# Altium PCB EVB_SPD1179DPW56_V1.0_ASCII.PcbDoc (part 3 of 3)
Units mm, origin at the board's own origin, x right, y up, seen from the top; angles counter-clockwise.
Board outline 135 x 90 mm, 4 copper layers (Top Layer, GND, L3, Bottom Layer), stack 0.603 mm thick; 336 components, 177 nets, 814 pads, 1056 vias.
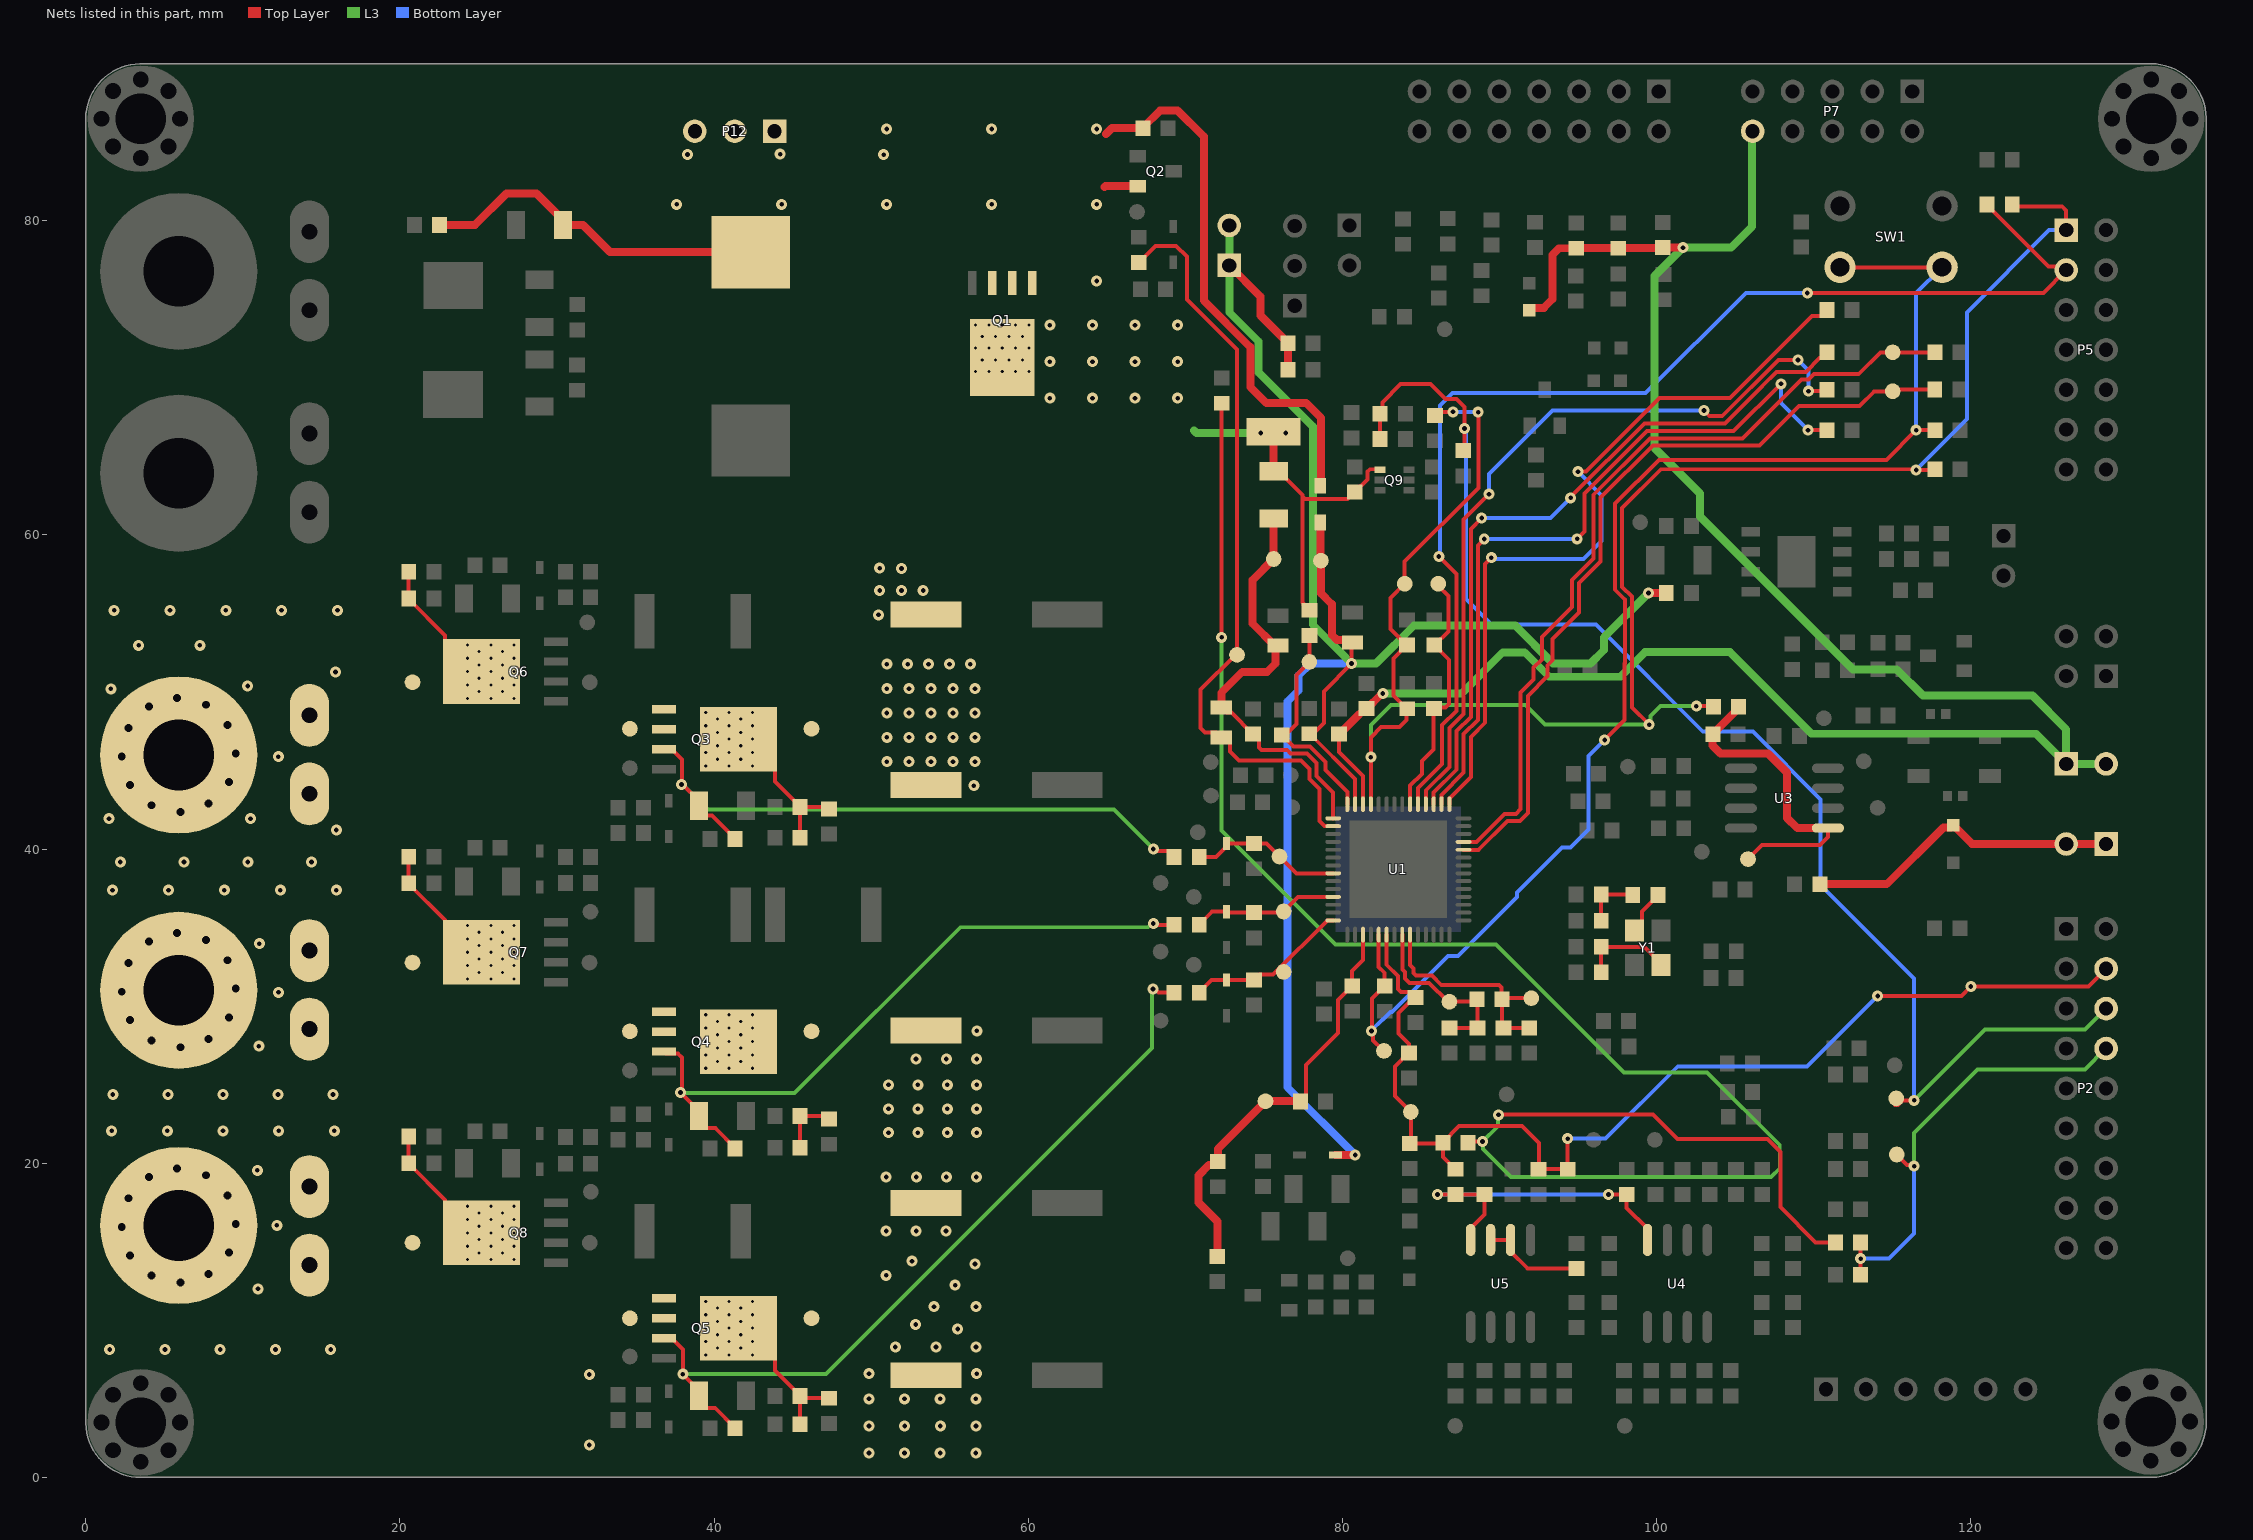
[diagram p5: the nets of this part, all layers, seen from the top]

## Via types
v1: diameter 0.7, hole 0.3, Top Layer to Bottom Layer, tented both sides, 810 vias
v2: diameter 0.5, hole 0.2, Top Layer to Bottom Layer, tented both sides, 161 vias
v3: diameter 0.9, hole 0.5, Top Layer to Bottom Layer, 60 vias
v4: diameter 0.6, hole 0.3, Top Layer to Bottom Layer, tented top, 25 vias

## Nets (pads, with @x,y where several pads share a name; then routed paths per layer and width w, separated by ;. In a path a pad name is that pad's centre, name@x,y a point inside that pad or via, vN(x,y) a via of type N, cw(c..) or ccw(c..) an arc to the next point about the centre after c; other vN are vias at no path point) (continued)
NetR107_1: R107.1 R108.1 R109.1 | length 123.1
  Top Layer w0.254: v1(72.314,53.487) R109.1@72.314,68.39 R109.1@72.466,68.237 ; R107.1@87.998,21.311 88.072,21.384 v1(88.925,21.384) ; v1(89.941,23.089) 89.967,23.114 99.771,23.114 101.346,21.539 107.075,21.539 107.885,20.729 107.885,17.207 110.132,14.961 R108.1@111.392,14.961 R108.1@111.392,14.986
  L3 w0.254: v1(72.314,53.487) 72.314,41.173 79.553,33.934 89.789,33.934 97.942,25.781 103.226,25.781 107.848,21.158 107.848,19.681 107.293,19.126 90.729,19.126 88.961,20.894 88.961,21.349 v1(88.925,21.384) 89.899,22.358 89.899,23.046 v1(89.941,23.089)
NetR110_2: R110.2 U5.6 U5.7 | length 6.6
  Top Layer w0.254: U5.7@89.443,15.117 U5.6@90.713,15.117 90.713,14.388 91.804,13.297 R110.2@94.904,13.297
NetR123_1: R123.1 Y1.3 | length 2.9
  Top Layer w0.254: Y1.3@98.591,34.831 99.064,35.304 99.064,36.034 100.089,37.059 R123.1@100.089,37.084
NTCAD: C73.2 P2.8 R108.2 TP51.1 | length 28.5
  Top Layer w0.254: C73.2@112.992,12.903 R108.2@112.992,14.961 R108.2@112.992,14.986 ; TP51.1@115.3,20.559 115.962,19.897 116.323,19.897 v1(116.408,19.812) v1@116.288,19.812
  L3 w0.254: v1(116.408,19.812) 116.408,21.94 120.452,25.983 127.269,25.983 128.591,27.305 P2.8@128.626,27.305
  Bottom Layer w0.254: v1(113.005,13.924) 114.812,13.924 116.408,15.519 v1(116.408,19.812)
PGAIN: C51.1 C53.2 R58.2 TP49.1 U1.50 | length 11.7
  Top Layer w0.254: U1.50@83.816,34.56 83.816,32.347 83.997,32.166 83.997,31.761 84.273,31.484 85.521,31.484 86.721,30.284 TP49.1@86.818,30.284 88.415,30.284 C51.1@88.567,30.437 88.605,30.399 R58.2@88.605,28.621 C53.2@86.827,28.621
PGAIP: C51.2 C52.2 R54.2 TP46.1 U1.51 | length 14.7
  Top Layer w0.254: U1.51@84.316,34.56 84.316,32.62 84.538,32.397 84.538,32.1 84.687,31.951 85.701,31.951 86.298,31.354 89.989,31.354 90.138,31.205 90.138,30.619 C51.2@90.243,30.513 ; C52.2@91.907,28.621 R54.2@90.256,28.621 90.167,28.71 C51.2@90.167,30.437 C51.2@90.243,30.513 ; TP46.1@92.034,30.513 C51.2@90.243,30.513
PWM/LIN: D18.2 P25.1 P25.2 R21.1 | length 20.3
  Top Layer w0.508: R21.1@110.401,37.77 114.656,37.77 118.271,41.385 118.751,41.385 D18.2@118.897,41.531 120.101,40.327 P25.2@126.086,40.327 P25.1@128.626,40.327
PWM/LIN_MCU: C78.2 R66.2 R84.1 R111.1 TP50.1 U1.45 | length 26.8
  Top Layer w0.254: R66.2@77.305,23.952 77.331,23.952 77.678,24.3 77.678,26.269 79.718,28.308 79.718,30.394 80.604,31.28 80.604,32.234 81.316,32.946 U1.45@81.316,34.56
  Top Layer w0.508: R84.1@72.044,14.075 72.044,16.293 70.842,17.495 70.842,19.229 71.496,19.883 71.848,19.883 R111.1@72.069,20.104 72.069,20.914 TP50.1@75.108,23.952 R66.2@77.305,23.952
TCK/SWC: R16.2 U1.18 | length 49.1
  Top Layer w0.254: U1.18@85.316,42.86 85.316,43.749 86.81,45.243 86.81,47.705 87.72,48.615 87.72,60.977 v1(89.339,62.597) ; v1(103.022,67.921) 103.383,67.561 104.176,67.561 107.76,71.145 v1(109.017,71.145) ; v1(109.677,69.159) 110.777,69.159 R16.2@110.858,69.24
  Bottom Layer w0.254: v1(89.339,62.597) 89.339,63.882 93.379,67.921 v1(103.022,67.921) ; v1(109.017,71.145) 109.677,70.485 v1(109.677,69.159)
TDI: R13.2 U1.15 | length 49.5
  Top Layer w0.254: U1.15@86.816,42.86 86.816,43.231 88.182,44.597 88.182,47.137 89.091,48.046 89.091,58.162 v1(89.483,58.554) ; v1(95.001,64.033) 95.518,64.033 100.201,68.716 104.685,68.716 109.916,73.947 110.51,73.947 110.858,74.295 R13.2@110.858,74.32
  Bottom Layer w0.254: v1(89.483,58.554) 89.558,58.479 95.369,58.479 96.514,59.624 96.514,62.521 v1(95.001,64.033)
TDO: R18.2 U1.16 | length 47.3
  Top Layer w0.254: U1.16@86.316,42.86 86.318,42.862 86.318,43.457 87.725,44.864 87.725,47.327 88.634,48.236 88.634,59.343 v1(89.035,59.744) ; v1(94.951,59.758) 95.409,60.216 95.409,62.631 99.391,66.614 104.909,66.614 v1(107.923,69.628) ; v1(109.652,66.675) 110.85,66.675 R18.2@110.858,66.667
  Bottom Layer w0.254: v1(89.035,59.744) 89.042,59.751 94.944,59.751 v1(94.951,59.758) ; v1(107.923,69.628) 107.923,68.404 v1(109.652,66.675)
TMS/SWD: R14.2 U1.17 | length 45.9
  Top Layer w0.254: U1.17@85.816,42.86 85.816,43.602 87.268,45.054 87.268,47.516 88.177,48.425 88.177,60.383 v1(88.876,61.082) ; v1(94.54,62.365) 94.54,62.409 99.235,67.103 104.372,67.103 106.731,69.463 106.731,69.47 107.645,70.383 109.513,70.383 110.385,71.255 110.51,71.255 110.858,71.603 R14.2@110.858,71.628
  Bottom Layer w0.254: v1(88.876,61.082) 93.257,61.082 v1(94.54,62.365)
TRSTn: P5.3 R12.1 U1.19 | length 77.1
  Top Layer w0.254: U1.19@84.816,42.86 84.816,43.895 86.353,45.432 86.353,47.895 87.262,48.804 87.262,57.518 v1(86.146,58.635) ; v1(109.607,75.413) 124.628,75.413 P5.3@126.086,76.87 125.847,77.108 124.964,77.108 121.052,81.02 R12.1@121.052,81.045
  Bottom Layer w0.254: v1(86.146,58.635) 86.227,58.716 86.227,68.246 87.015,69.033 99.309,69.033 105.689,75.413 v1(109.607,75.413)
UART_RX: R15.1 TP60.1 U1.11 | length 51.9
  Top Layer w0.254: U1.11@87.716,40.46 88.531,40.46 90.318,42.247 91.055,42.247 91.349,42.54 91.349,49.958 92.178,50.788 92.178,51.559 92.705,52.086 92.705,53.511 94.611,55.417 94.611,57.139 95.987,58.515 95.987,62.562 99.581,66.156 105.485,66.156 109.219,69.89 109.666,69.89 110.033,70.256 112.878,70.256 114.249,71.628 TP60.1@115.037,71.628 R15.1@117.729,71.628
UART_TX: R17.1 TP59.1 U1.10 | length 51.2
  Top Layer w0.254: U1.10@87.716,39.96 88.673,39.96 90.503,41.79 91.309,41.79 91.806,42.286 91.806,49.764 93.06,51.018 93.06,51.706 93.38,52.026 93.38,53.367 95.069,55.056 95.069,56.95 96.444,58.325 96.444,62.373 99.77,65.699 106.568,65.699 109.068,68.199 112.916,68.199 113.864,69.147 TP59.1@115.037,69.147 115.155,69.266 R17.1@117.716,69.266
VBAT: C35.2 C36.2 D12.1 D16.2 P11.1 P11.2 R49.1 R113.2 R114.1 TP55.1 U1.27 | length 122.2
  Top Layer w0.254: C36.2@77.9,47.347 77.925,47.347 80.816,44.456 U1.27@80.816,42.86 ; C36.2@78.127,47.322 78.829,48.024 78.829,50.05 80.582,51.804 v1(80.582,51.816) C35.2@80.582,53.101
  Top Layer w0.508: P11.1@72.803,77.168 74.797,75.174 74.797,73.971 76.544,72.224 R113.2@76.544,72.199 76.541,72.196 76.541,70.528 R114.1@76.537,70.524 ; D12.1@78.595,60.798 78.595,58.412 TP55.1@78.638,58.369 78.638,56.286 79.329,55.596 79.329,53.646 79.659,53.316 80.367,53.316 C35.2@80.582,53.101 ; D16.2@79.559,20.523 D16.2@79.559,20.523 80.82,20.522 v1(80.821,20.521) ; v1(99.492,56.312) R49.1@100.622,56.312
  L3 w0.508: P11.2@72.803,79.221 P11.1@72.803,77.168 72.803,74.181 74.675,72.309 74.675,70.345 78.121,66.9 78.121,54.29 80.582,51.828 v1(80.582,51.816) ; v1@80.594,51.816 82.138,51.816 84.572,54.25 90.984,54.25 93.419,51.816 95.8,51.816 96.649,52.665 96.649,53.469 v1(99.492,56.312)
  Bottom Layer w0.508: v1(80.582,51.816) 77.968,51.816 77.195,51.043 77.195,50.085 76.497,49.387 76.497,24.845 v1(80.821,20.521)
VBAT1: C9.2 C10.1 C11.2 D12.2 L1.2 P12.1 P12.2 P12.3 Q1.1 Q1.2 Q1.3 Q2.2 | length 58.9
  Top Layer w0.508: C11.2@22.517,79.731 24.77,79.731 26.781,81.742 28.694,81.742 30.059,80.377 30.38,80.056 C10.1@30.38,79.731 31.648,79.731 33.37,78.009 L1.2@42.342,78.009 ; 64.872,82.169 64.912,82.21 Q2.2@66.973,82.21 ; 64.948,85.522 65.329,85.903 C9.2@67.297,85.903 67.297,85.928 68.403,87.033 69.507,87.033 71.178,85.362 71.178,74.923 74.143,71.958 74.143,69.418 75.159,68.402 77.699,68.402 78.638,67.462 D12.2@78.638,63.143
  other v1: 64.364,76.175 37.617,81.051 44.304,81.051 50.99,81.051 57.677,81.051 64.364,81.051 50.799,84.212 38.309,84.222 44.209,84.243 50.99,85.852 57.677,85.852 64.364,85.852
VBAT_D: C1.1 C5.1 C6.1 C14.1 C15.1 C16.2 C17.2 C18.2 C20.2 C21.2 C22.2 C56.1 C68.1 C69.1 Q1.5 Q3.5 Q4.5 Q5.5 Q9.4 R39.2 R43.1 R93.1 TP4.1 TP5.1 TP6.1 TP40.1 | length 45.2
  Top Layer w0.254: v2(42.443,7.804) 43.631,7.804 43.866,7.569 43.866,6.819 45.479,5.207 C22.2@45.479,5.182 ; v2(42.443,45.301) 43.631,45.301 43.866,45.066 43.866,44.316 45.479,42.704 C20.2@45.479,42.679 ; C69.1@45.479,3.378 C22.2@45.479,5.182 ; C68.1@45.479,20.996 C21.2@45.479,23.003 47.13,23.003 C16.2@47.32,22.812 ; C56.1@45.479,40.723 C20.2@45.479,42.679 ; C18.2@47.32,5.042 45.618,5.042 C22.2@45.479,5.182 ; C17.2@47.32,42.564 47.206,42.679 C20.2@45.479,42.679 ; R43.1@75.625,64.06 75.95,64.06 77.47,62.54 77.47,62.461 ; R39.2@77.911,55.207 77.886,55.207 77.538,55.555 77.538,55.635 77.47,55.704 77.47,62.461 ; Q9.4@82.392,64.15 82.337,64.094 82.245,64.186 81.759,64.186 81.61,64.037 81.61,63.532 81.154,63.076 81.104,63.076 80.335,62.306 77.625,62.306 77.47,62.461
  Top Layer w0.508: R43.1@75.625,64.06 TP40.1@75.625,66.573
  L3 w0.508: 70.561,66.65 70.714,66.497 v1(74.799,66.497) v1(76.399,66.497)
  other v1: 49.86,1.549 52.129,1.549 54.398,1.549 56.667,1.549 32.055,2.057 49.86,3.277 52.132,3.277 54.404,3.277 56.676,3.277 49.86,5.004 52.129,5.004 54.398,5.004 56.667,5.004 32.055,6.553 49.86,6.604 56.718,6.604 51.537,8.306 54.131,8.306 56.676,8.306 55.506,9.451 52.832,9.728 54,10.871 56.676,10.871 55.347,12.243 50.961,12.866 56.617,13.589 52.603,13.767 50.961,15.686 52.866,15.686 54.771,15.686 50.961,19.126 52.874,19.126 54.787,19.126 56.701,19.126 51.105,21.946 52.976,21.946 54.847,21.946 56.718,21.946 51.105,23.47 52.976,23.47 54.847,23.47 56.718,23.47 51.105,24.994 52.976,24.994 54.847,24.994 56.718,24.994 52.857,26.645 54.788,26.645 56.718,26.645 56.726,28.436 56.54,44.044 51.003,45.568 52.407,45.568 53.81,45.568 55.213,45.568 56.617,45.568 51.003,47.12 52.407,47.12 53.81,47.12 55.213,47.12 56.617,47.12 51.003,48.673 52.407,48.673 53.81,48.673 55.213,48.673 56.617,48.673 51.003,50.216 52.407,50.216 53.81,50.216 55.213,50.216 56.617,50.216 51.003,51.779 52.33,51.779 53.657,51.779 54.985,51.779 56.312,51.779 50.47,54.915 50.546,56.464 51.93,56.464 53.315,56.464 51.93,57.861 50.546,57.887 61.377,68.707 64.092,68.707 66.806,68.707 69.52,68.707 61.377,71.031 64.092,71.031 66.806,71.031 69.52,71.031 61.377,73.355 64.092,73.355 66.806,73.355 69.52,73.355
  other v2: 39.472,7.804 40.957,7.804 40.215,8.23 41.7,8.23 39.472,8.655 40.957,8.655 42.443,8.655 40.215,9.081 41.7,9.081 39.472,9.506 40.957,9.506 42.443,9.506 40.215,9.931 41.7,9.931 39.472,10.357 40.957,10.357 42.443,10.357 40.215,10.782 41.7,10.782 39.472,11.208 40.957,11.208 42.443,11.208 39.472,26.053 40.957,26.053 42.443,26.053 40.215,26.478 41.7,26.478 39.472,26.904 40.957,26.904 42.443,26.904 40.215,27.329 41.7,27.329 39.472,27.754 40.957,27.754 42.443,27.754 40.215,28.18 41.7,28.18 39.472,28.605 40.957,28.605 42.443,28.605 40.215,29.031 41.7,29.031 39.472,29.456 40.957,29.456 42.443,29.456 39.472,45.301 40.957,45.301 40.215,45.727 41.7,45.727 39.472,46.152 40.957,46.152 42.443,46.152 40.215,46.577 41.7,46.577 39.472,47.003 40.957,47.003 42.443,47.003 40.215,47.428 41.7,47.428 39.472,47.854 40.957,47.854 42.443,47.854 40.215,48.279 41.7,48.279 39.472,48.705 40.957,48.705 42.443,48.705 56.648,70.409 57.499,70.409 58.35,70.409 59.201,70.409 60.052,70.409 57.074,71.152 57.925,71.152 58.776,71.152 59.627,71.152 56.648,71.895 57.499,71.895 58.35,71.895 59.201,71.895 60.052,71.895 57.074,72.638 57.925,72.638 58.776,72.638 59.627,72.638 56.648,73.381 57.499,73.381 58.35,73.381 59.201,73.381 60.052,73.381
VBATCP: C38.2 C39.2 C49.2 R43.2 TP56.1 U1.29 | length 27.4
  Top Layer w0.254: C49.2@72.292,49.009 72.615,48.686 72.935,48.686 74.287,47.334 C39.2@74.312,47.334 74.337,47.334 74.685,46.986 74.685,46.477 74.86,46.302 76.492,46.302 76.704,46.091 77.76,46.091 78.358,45.493 78.358,44.666 79.416,43.608 U1.29@79.416,41.96
  Top Layer w0.508: C49.2@72.292,49.009 72.292,49.949 73.634,51.291 75.216,51.291 75.756,51.831 C38.2@75.756,52.81 ; R43.2@75.625,61.06 TP56.1@75.625,58.471 74.293,57.139 74.293,54.351 75.683,52.961 C38.2@75.908,52.961
VBATD_DIV: C83.2 P2.6 R88.1 R98.1 TP61.1 | length 87.9
  Top Layer w0.254: R88.1@82.41,66.116 R98.1@82.41,67.716 82.546,67.852 82.546,68.449 83.713,69.616 85.607,69.616 86.567,68.656 87.267,68.656 87.782,68.141 v1(87.782,66.777) 87.782,65.442 87.709,65.368 C83.2@87.701,65.368 ; TP61.1@115.189,23.724 115.391,23.724 115.67,24.003 v1(116.408,24.003)
  L3 w0.254: v1(116.408,24.003) 120.911,28.506 127.287,28.506 P2.6@128.626,29.845
  Bottom Layer w0.254: v1(87.782,66.777) 87.862,66.697 87.862,55.938 89.511,54.288 96.148,54.288 102.947,47.49 106.134,47.49 110.457,43.167 110.457,37.726 116.408,31.775 v1(116.408,24.003)
VBATM: C37.2 R39.1 TP57.1 U1.28 | length 13.8
  Top Layer w0.254: C37.2@76.144,47.268 76.169,47.268 76.892,46.545 77.948,46.545 78.939,45.554 78.939,45.024 80.316,43.647 U1.28@80.316,42.86 ; C37.2@76.495,47.146 76.495,47.379 77.073,47.957 77.073,51.089 TP57.1@77.902,51.918 77.902,53.597 R39.1@77.911,53.607
VCAP12: C29.2 C30.2 TP54.1 U1.20 | length 16.5
  Top Layer w0.254: U1.20@84.316,42.86 84.316,44.042 85.068,44.794 85.068,45.603 85.801,46.336 85.801,48.911 C30.2@85.833,48.942 85.901,49.01 86.575,49.01 86.805,49.24 86.805,52.056 C29.2@85.877,52.984 ; C29.2@85.852,52.984 C29.2@85.877,52.984 ; TP54.1@86.106,56.896 86.106,56.752 86.746,56.112 86.746,53.853 C29.2@85.877,52.984
VCP: C49.1 R5.1 TP58.1 U1.30 | length 49.1
  Top Layer w0.254: R5.1@67.031,77.356 67.056,77.356 68.106,78.406 69.422,78.406 70.107,77.721 70.107,75.006 73.295,71.818 TP58.1@73.295,52.365 73.197,52.365 70.983,50.151 70.983,47.7 71.251,47.432 71.969,47.432 C49.1@72.292,47.109 72.517,47.109 72.84,46.786 72.84,46.216 73.422,45.634 77.374,45.634 77.901,45.107 77.901,44.476 78.541,43.836 78.541,41.789 78.869,41.462 79.414,41.462 U1.30@79.416,41.46
VDD3: C40.2 C41.2 C72.2 P2.4 R82.1 R96.1 R106.2 R107.2 TP53.1 U1.48 | length 71.2
  Top Layer w0.254: U1.48@82.816,34.56 82.816,32.639 83.543,31.911 83.543,31.107 83.749,30.901 84.305,30.901 C41.2@84.653,30.553 84.555,30.455 C41.2@84.555,30.591 ; C40.2@84.222,27.048 83.339,26.165 83.339,24.29 TP53.1@84.363,23.266 84.363,21.336 R106.2@84.287,21.26 86.347,21.26 R107.2@86.398,21.311 ; C40.2@84.271,27.385 84.246,27.385 84.246,27.586 83.581,28.25 83.581,29.581 C41.2@84.455,30.455 ; R96.1@87.208,19.621 87.183,19.621 86.398,20.406 R107.2@86.398,21.311 ; v1(94.345,21.567) C72.2@94.345,19.621 R82.1@92.491,19.621 92.466,19.621 92.527,19.682 92.527,21.283 91.443,22.367 87.429,22.367 86.398,21.336 R107.2@86.398,21.311 ; v1(114.08,30.654) 119.409,30.654 v1(120.01,31.254) 127.495,31.254 P2.4@128.626,32.385
  Bottom Layer w0.254: v1(94.345,21.567) 96.769,21.567 101.355,26.153 109.579,26.153 v1(114.08,30.654)
VDD5: C31.2 C32.2 P5.1 R12.2 R20.2 R48.2 R97.1 TP52.1 U1.25 | length 118.9
  Top Layer w0.254: U1.25@81.816,42.86 v1(81.816,45.859) 81.816,47.113 82.464,47.761 83.63,47.761 84.093,48.224 84.093,48.902 C32.2@84.128,48.937 84.103,48.937 83.259,49.782 83.259,52.146 C31.2@84.097,52.984 ; C31.2@84.122,52.984 C31.2@84.097,52.984 ; R97.1@85.902,67.601 86.144,67.843 v1(87.046,67.843) ; R97.1@85.902,67.652 R97.1@86.003,67.754 ; v1(88.646,67.818) 88.671,67.793 88.671,63.004 83.972,58.305 TP52.1@83.972,56.896 83.07,55.994 83.07,54.011 C31.2@84.097,52.984 ; v1(99.539,47.927) 98.436,49.03 98.436,51.632 98.438,51.634 98.438,56.081 97.815,56.703 97.815,61.709 100.292,64.186 116.487,64.186 v1(116.532,64.141) 117.684,64.141 R20.2@117.729,64.186 ; v1(102.54,49.098) 103.594,49.098 R48.2@103.619,49.073 ; R12.2@122.652,81.045 122.768,80.929 125.811,80.929 126.086,80.654 P5.1@126.086,79.41
  L3 w0.254: v1(81.816,45.859) 81.816,47.889 83.093,49.166 91.652,49.166 92.891,47.927 v1(99.539,47.927) 99.625,48.012 99.625,48.474 100.249,49.098 v1(102.54,49.098)
  Bottom Layer w0.254: v1(87.046,67.843) 87.058,67.831 88.633,67.831 v1(88.646,67.818) ; v1(116.532,64.141) 119.761,67.37 119.761,74.168 125.003,79.41 P5.1@126.086,79.41
VDD5EXT: C33.2 C84.2 D19.1 P7.10 P8.1 P8.2 R117.2 R118.2 R119.2 U1.26 | length 134.7
  Top Layer w0.254: C33.2@79.81,47.322 C33.2@79.785,47.322 79.785,46.195 81.316,44.664 U1.26@81.316,42.86 ; C84.2@81.09,48.602 81.165,48.602 C84.2@81.513,48.95 ; C84.2@81.538,48.95 C84.2@81.563,48.95
  Top Layer w0.508: C33.2@79.81,47.322 C84.2@81.09,48.602 ; C84.2@81.563,48.95 82.441,49.828 82.541,49.828 82.582,49.869 v1(82.582,49.912) ; D19.1@91.905,74.32 92.051,74.466 92.828,74.466 93.371,75.009 93.371,77.831 93.796,78.256 R119.2@94.889,78.256 ; R119.2@94.889,78.256 97.57,78.257 97.591,78.279 100.376,78.279 R117.2@100.397,78.299 101.688,78.299 v1(101.692,78.296)
  L3 w0.508: v1(82.582,49.912) 87.598,49.912 90.218,52.533 91.61,52.533 93.167,50.975 97.712,50.975 99.274,52.536 104.676,52.536 109.867,47.346 124.165,47.346 P8.1@126.086,45.425 ; P7.10@106.122,85.704 106.094,85.675 106.094,79.635 104.755,78.296 v1(101.692,78.296) 99.879,76.483 99.879,65.538 102.777,62.64 102.777,61.179 112.512,51.444 115.293,51.444 116.964,49.773 123.937,49.773 126.086,47.625 P8.1@126.086,45.425 ; P8.2@128.626,45.425 P8.1@126.086,45.425
VIO: C61.2 R48.1 TP32.1 U3.5 | length 20.6
  Top Layer w0.254: TP32.1@105.828,39.366 106.711,40.25 110.408,40.25 110.916,40.758 U3.5@110.916,41.337
  Top Layer w0.508: R48.1@105.219,49.073 104.998,48.852 104.998,48.75 103.594,47.345 C61.2@103.594,47.32 103.566,47.292 103.566,46.601 104.078,46.089 107.107,46.089 108.314,44.882 108.314,41.989 108.965,41.337 U3.5@110.916,41.337
VOP: C70.2 C71.2 R96.2 U4.8 U5.8 | length 21.8
  Top Layer w0.254: v1(86.055,18.009) 87.195,18.009 R96.2@87.208,18.021 C70.2@89.057,18.021 89.057,16.73 88.173,15.845 U5.8@88.173,15.117 ; v1(96.952,18.009) 98.093,18.009 C71.2@98.106,18.021 98.106,17.165 99.427,15.845 U4.8@99.427,15.117
  Bottom Layer w0.254: v1(86.055,18.009) v1(96.952,18.009)
VPX_U: C28.1 C43.2 C79.1 P16.1 pad.1@5.918,16.042 Q5.1 Q5.2 Q5.3 Q8.5 R31.1 R37.2 TP15.1 TP17.1 | length 58.6
  Top Layer w0.254: C79.1@20.561,21.7 C43.2@20.561,19.998 20.561,19.973 22.879,17.655 22.879,17.501 23.114,17.266 v2(24.301,17.266) ; Q5.3@36.805,8.865 37.3,8.865 38.015,8.15 v1(38.015,6.568) 38.015,6.555 39.038,5.532 R37.2@39.038,5.207 39.038,4.882 39.486,4.434 40.054,4.434 41.338,3.149 C28.1@41.338,3.124 ; v1(67.947,31.091) 68.068,31.091 68.298,30.861 R31.1@69.288,30.861
  L3 w0.254: v1(38.015,6.568) 38.025,6.579 47.117,6.579 67.885,27.347 67.885,31.03 v1(67.947,31.091)
  other v1: 1.52,8.148 5.038,8.148 8.556,8.148 12.074,8.148 15.592,8.148 10.969,12.009 12.163,16.048 10.918,19.553 1.647,22.068 5.191,22.068 8.734,22.068 12.277,22.068 15.82,22.068
  other v2: 24.301,13.862 25.787,13.862 27.273,13.862 25.044,14.288 26.53,14.288 24.301,14.713 25.787,14.713 27.273,14.713 25.044,15.138 26.53,15.138 24.301,15.564 25.787,15.564 27.273,15.564 25.044,15.989 26.53,15.989 24.301,16.415 25.787,16.415 27.273,16.415 25.044,16.84 26.53,16.84 25.787,17.266 27.273,17.266
  other v3: 6.02,12.409 4.19,12.845 7.822,12.947 2.823,14.138 9.115,14.313 2.286,15.94 9.55,16.143 2.722,17.77 9.013,17.946 4.014,19.136 7.646,19.238 5.817,19.674
VPX_U0: C19.2 D3.1 R31.2 TP7.1 U1.42 | length 10.5
  Top Layer w0.254: R31.2@70.888,30.861 70.888,30.886 71.673,31.671 D3.1@72.628,31.671 72.635,31.664 C19.2@74.381,31.664 74.729,32.012 75.598,32.012 79.045,35.46 U1.42@79.416,35.46
VPX_V: C27.1 C42.2 C76.1 P15.1 pad.1@5.918,31.017 Q4.1 Q4.2 Q4.3 Q7.5 R33.2 R38.1 TP14.1 TP16.1 | length 51.5
  Top Layer w0.254: C76.1@20.561,39.521 C42.2@20.561,37.819 20.561,37.794 22.879,35.477 22.879,35.37 23.114,35.135 v2(24.301,35.135) ; Q4.3@36.805,27.113 36.944,26.973 37.703,26.973 37.946,26.731 37.946,24.601 37.855,24.511 39.038,23.328 R33.2@39.038,23.003 39.038,22.678 39.486,22.23 40.079,22.23 41.338,20.971 C27.1@41.338,20.946 ; v1(67.97,35.261) 68.052,35.179 R38.1@69.288,35.179
  L3 w0.254: v1(37.86,24.511) 37.886,24.486 45.136,24.486 55.677,35.027 67.616,35.027 67.85,35.261 v1(67.97,35.261)
  other v1: 1.723,24.379 5.229,24.379 8.734,24.379 12.239,24.379 15.744,24.379 11.02,27.452 12.264,30.881 11.045,33.98 1.698,37.384 5.26,37.384 8.823,37.384 12.385,37.384 15.947,37.384
  other v2: 24.301,31.731 25.787,31.731 27.273,31.731 25.044,32.156 26.53,32.156 24.301,32.582 25.787,32.582 27.273,32.582 25.044,33.007 26.53,33.007 24.301,33.433 25.787,33.433 27.273,33.433 25.044,33.858 26.53,33.858 24.301,34.284 25.787,34.284 27.273,34.284 25.044,34.709 26.53,34.709 25.787,35.135 27.273,35.135
  other v3: 6.02,27.385 4.19,27.821 7.822,27.922 2.823,29.113 9.115,29.289 2.286,30.916 9.55,31.119 2.722,32.745 9.013,32.921 4.014,34.112 7.646,34.214 5.817,34.649
VPX_V0: C23.2 D4.1 R38.2 TP9.1 U1.39 | length 9.3
  Top Layer w0.254: R38.2@70.888,35.179 70.888,35.204 71.698,36.014 D4.1@72.628,36.014 72.689,35.954 C23.2@74.381,35.954 76.184,35.954 TP9.1@76.26,36.03 77.19,36.96 U1.39@79.416,36.96
VPX_W: C25.2 C26.1 C75.1 P14.1 pad.1@5.918,45.993 Q3.1 Q3.2 Q3.3 Q6.5 R32.2 R44.1 TP13.1 TP18.1 | length 48.4
  Top Layer w0.254: C75.1@20.561,57.658 C25.2@20.561,55.956 20.561,55.931 22.879,53.614 22.879,53.238 23.114,53.003 v2(24.301,53.003) ; Q3.3@36.805,46.362 37.3,46.362 37.961,45.701 37.961,44.159 v1(37.922,44.12) 37.998,44.12 39.038,43.08 R32.2@39.038,42.755 39.038,42.587 39.486,42.139 39.871,42.139 41.338,40.672 C26.1@41.338,40.647 ; v1(67.97,40.005) 68.091,40.005 68.226,39.87 68.94,39.87 69.288,39.522 R44.1@69.288,39.497
  L3 w0.254: v1(37.922,44.12) 38.024,44.12 39.624,42.52 65.456,42.52 v1(67.97,40.005)
  other v1: 2.202,39.181 6.258,39.181 10.313,39.181 14.369,39.181 15.951,41.224 1.473,41.935 10.483,41.935 12.261,45.886 1.593,50.204 10.305,50.382 15.893,51.271 3.371,52.973 7.257,52.973 1.803,55.208 5.357,55.208 8.912,55.208 12.466,55.208 16.02,55.208
  other v2: 24.301,49.6 25.787,49.6 27.273,49.6 25.044,50.025 26.53,50.025 24.301,50.451 25.787,50.451 27.273,50.451 25.044,50.876 26.53,50.876 24.301,51.302 25.787,51.302 27.273,51.302 25.044,51.727 26.53,51.727 24.301,52.153 25.787,52.153 27.273,52.153 25.044,52.578 26.53,52.578 25.787,53.003 27.273,53.003
  other v3: 6.02,42.361 4.19,42.796 7.822,42.898 2.823,44.089 9.115,44.265 2.286,45.891 9.55,46.094 2.722,47.721 9.013,47.897 4.014,49.088 7.646,49.189 5.817,49.625
VPX_W0: C24.2 D5.1 R44.2 TP44.1 U1.36 | length 9.8
  Top Layer w0.254: R44.2@70.888,39.497 71.957,39.497 72.628,40.168 D5.1@72.628,40.358 72.635,40.351 C24.2@74.381,40.351 75.18,40.351 TP44.1@76,39.531 77.071,38.46 U1.36@79.416,38.46
XIN: C12.2 R1.1 Y1.1 | length 6
  Top Layer w0.254: C12.2@96.482,32.156 R1.1@96.482,33.782 99.24,33.782 100.291,32.731 Y1.1@100.291,32.631
XOUT: C13.2 R120.1 R123.2 | length 3.7
  Top Layer w0.254: R120.1@96.482,35.433 C13.2@96.482,37.109 98.463,37.109 R123.2@98.489,37.084 R123.2@98.489,37.059
XRSTn: C7.2 R19.1 SW1.3 SW1.4 TP1.1 U1.47 | length 89.3
  Top Layer w0.254: U1.47@82.316,34.56 82.316,32.492 82.678,32.13 82.678,31.28 81.876,30.478 81.876,28.441 v1(81.856,28.42) 81.941,28.335 81.941,27.831 82.509,27.263 TP1.1@82.509,27.153 ; v1(96.703,46.954) 97.979,48.23 97.979,51.821 97.981,51.823 97.981,55.891 97.358,56.514 97.358,61.994 100.149,64.785 114.645,64.785 v1(116.535,66.675) 117.721,66.675 R19.1@117.729,66.667 ; SW1.3@111.685,77.044 SW1.4@118.185,77.044
  Bottom Layer w0.254: v1(81.856,28.42) 81.856,28.469 82.547,29.16 82.596,29.16 83.062,29.626 83.151,29.626 86.728,33.203 87.356,33.203 91.117,36.964 91.117,37.242 93.985,40.11 94.529,40.11 95.665,41.246 95.665,45.916 v1(96.703,46.954) ; v1(116.535,66.675) 116.535,75.394 SW1.4@118.185,77.044
pads on no net: SC1.1 SC2.1 SC3.1 SC4.1 U2.3 U2.4 U2.6

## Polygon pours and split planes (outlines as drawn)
GND on Top Layer "GND_L01_P087" (solid, remove dead copper, pour order 87): 80.647,88.701 81.239,89.293 81.239,89.968 125.065,89.968 127.633,87.4 127.633,84.998 129.862,82.769 133.616,82.769 134.998,81.387 134.998,8.392 133.727,7.121 129.746,7.121 127.714,5.089 127.714,1.71 126.013,0.009 81.88,0.009 80.663,1.225 80.663,5.803 79.226,7.24 79.224,7.238 72.322,7.238 71.543,8.017 71.543,82.105 72.298,82.86 79.257,82.86 80.672,84.275
VPX_W on Top Layer "VPX_W_L01_P002" (solid, remove dead copper, pour order 2): 0.045,56.032 26.776,56.032 28.151,54.686 28.151,49.276 28.671,48.768 32.771,48.768 33.29,49.276 38.506,49.276 38.506,46.076 31.032,38.76 0.045,38.76
GND on Top Layer "NONET_L-01_P-001" (solid, remove dead copper, pour order 21): 1.885,82.758 0.826,81.772 0.826,71.924 1.703,71.107 18.483,71.107 20.464,72.951 35.613,72.951 35.789,73.114 35.789,82.285 25.48,82.285 23.474,84.152 23.474,89.115 7.229,89.115 7.229,84.731 5.108,82.758
GND on Top Layer "GND_L01_P095" (solid, remove dead copper, pour order 95): 94.015,38.67 99.659,38.67 100.976,37.353 100.976,32.024 99.958,31.006 95.056,31.006 92.921,33.142 92.921,37.847
GND on Top Layer "GND_L01_P079" (solid, pour order 79): 47.167,36.572 47.167,39.918 47.456,40.207 58.292,40.207 58.292,60.222 59.012,60.942 59.045,60.909 71.263,60.909 71.263,0.06 71.259,0.055 71.253,0.061 58.217,0.061 58.217,29.218 58.221,29.222 56.601,30.842 47.229,30.842 47.176,30.895 47.176,35.052 50.052,35.052 50.281,35.281 50.28,35.281 50.28,36.382 50.085,36.577 50.082,36.574 47.167,36.574
VBAT1 on Top Layer "VBAT1_L01_P014" (solid, remove dead copper, pour order 14): 36.246,88.468 36.246,73.025 63.729,73.025 65.557,74.854 65.557,88.468
KL30 on Top Layer "KL30_L01_P013" (solid, remove dead copper, pour order 13): 0.004,70.383 0.004,56.515 26.731,56.515 29.766,59.538 49.072,59.538 49.174,59.639 49.174,72.238 48.996,72.415 20.432,72.415 18.545,70.536 0.157,70.536
VBAT_D on Top Layer "VBAT_D_L01_P012" (solid, remove dead copper, pour order 12): 39.091,49.632 38.735,49.276 38.735,44.526 42.393,40.869 57.252,40.869 57.937,41.554 57.937,60.096 59.004,61.163 71.247,61.163 71.247,73.076 69.901,74.422 51.613,74.422 49.657,72.466 49.657,51.308 47.981,49.632
IWS+ on Top Layer "IWS+_L01_P010" (solid, remove dead copper, pour order 10): 28.753,54.915 28.753,54.661 28.575,54.483 28.575,49.428 29.185,48.819 32.664,48.819 33.604,49.759 38.608,49.759 38.608,53.67 38.506,53.772 35.89,53.772 35.763,53.899 35.763,54.991 36.144,55.372 38.532,55.372 38.557,55.397 38.557,58.953 38.506,59.004 32.766,59.004 31.521,57.76
IBS+ on Top Layer "IBS+_L01_P008" (solid, remove dead copper, pour order 8): 39.472,40.107 38.964,39.599 38.964,36.627 41.046,36.627 41.275,36.398 41.275,35.179 41.148,35.052 38.964,35.052 38.964,31.09 39.218,30.836 46.584,30.836 46.939,31.191 46.939,35.052 44.475,35.052 44.171,35.357 44.171,36.449 44.298,36.576 46.939,36.576 46.939,40.056 46.888,40.107
IVS+ on Top Layer "IVS+_L01_P007" (solid, remove dead copper, pour order 7): 28.626,36.373 28.626,31.217 29.261,30.582 38.125,30.582 38.43,30.886 38.43,34.9 38.303,35.027 36.17,35.027 35.814,35.382 35.814,36.373 36.068,36.627 38.405,36.627 38.481,36.703 38.481,39.776 37.77,40.488 32.487,40.488 28.88,36.881
VBAT_D on Top Layer "VBAT_D_L01_P006" (solid, remove dead copper, pour order 6): 38.456,11.913 38.456,4.343 41.758,1.041 51.054,1.041 51.054,12.548 49.708,13.894 49.555,13.741 49.555,13.386 48.743,12.573 39.116,12.573
VBAT_D on Top Layer "VBAT_D_L01_P005" (solid, remove dead copper, pour order 5): 38.938,30.455 38.71,30.226 38.71,24.816 40.462,23.063 45.872,23.063 49.276,19.66 49.276,1.067 58.014,1.067 58.014,28.931 56.49,30.455
IBS+ on Top Layer "IBS+_L01_P004" (solid, remove dead copper, pour order 4): 39.268,20.371 38.989,20.091 38.989,16.485 41.123,16.485 41.402,16.205 41.402,15.164 41.148,14.91 38.989,14.91 38.989,12.751 48.235,12.751 48.514,13.03 48.514,20.117 48.26,20.371
IUS+ on Top Layer "IUS+_L01_P003" (solid, remove dead copper, pour order 3): 28.677,13.259 29.007,12.929 38.405,12.929 38.405,14.91 35.941,14.91 35.916,14.935 35.916,16.231 36.17,16.485 38.405,16.485 38.405,20.168 38.024,20.549 30.734,20.549 28.677,18.491
VPX_V on Top Layer "VPX_V_L01_P001" (solid, remove dead copper, pour order 1): 0.015,38.125 26.474,38.125 28.197,36.424 28.197,30.963 28.917,30.251 38.2,30.251 38.354,30.099 38.354,25.603 37.737,24.994 35.834,23.114 0.041,23.114 0.015,23.139
VPX_U on Top Layer "VPX_U_L01_P000" (solid, remove dead copper, pour order 0): 0.005,22.809 23.976,22.809 28.071,18.796 28.071,13.157 28.874,12.37 38.1,12.37 38.1,7.95 37.4,7.264 0.005,7.264
IBS+ on Top Layer "IBS+_L01_P011" (solid, remove dead copper, pour order 11): 39.218,58.979 39.141,58.903 39.141,55.397 39.167,55.372 41.123,55.372 41.3,55.194 41.3,53.924 41.148,53.772 38.938,53.772 38.887,53.721 38.887,49.835 47.828,49.835 49.301,51.308 49.301,58.852 49.174,58.979
GND on Top Layer "GND_L01_P059" (solid, remove dead copper, pour order 59): 30.632,89.027 30.632,84.963 28.219,82.55 35.355,82.55 35.738,82.933 35.738,88.748 35.458,89.027
GND on Bottom Layer "GND" (solid, remove dead copper, pour order 86): 80.65,88.7 80.65,88.747 81.887,89.984 125.21,89.984 127.641,87.552 127.641,84.966 127.647,84.966 129.924,82.688 133.727,82.688 134.992,81.423 134.992,8.374 133.771,7.153 133.768,7.156 129.7,7.156 127.707,5.162 127.707,1.814 125.896,0.004 81.855,0.004 80.602,1.257 80.602,7.28 80.163,7.719 74.487,7.719 73.677,6.909 72.521,6.909 71.604,7.827 71.604,82.121 71.605,82.121 72.337,82.852 79.305,82.852 80.65,84.198
GND on Bottom Layer "NONET_L-01_P-001" (solid, remove dead copper, pour order 45): 1.041,82.982 1.041,71.069 1.295,70.815 18.415,70.815 20.396,72.796 49.098,72.796 51.765,75.463 51.841,75.387 71.349,75.387 71.349,88.875 70.968,89.256 30.886,89.256 30.632,89.002 30.632,85.014 28.778,83.16 25.222,83.16 23.368,85.014 23.368,89.586 7.137,89.586 7.137,84.988 5.131,82.982
VPX_V on Bottom Layer "NONET_L-01_P-001" (solid, remove dead copper, pour order 19): 1.041,38.318 1.041,23.317 28.092,23.317 28.524,23.749 28.524,37.871 28.158,38.238
KL30 on Bottom Layer "NONET_L-01_P-001" (solid, remove dead copper, pour order 32): 1.118,70.587 1.118,56.54 27.711,56.54 28.575,57.404 28.575,60.706 18.669,70.612 1.143,70.612
VPX_W on Bottom Layer "NONET_L-01_P-001" (solid, remove dead copper, pour order 18): 27.915,56.032 1.016,56.032 1.016,38.735 27.94,38.735 28.473,39.268 28.473,55.474
VPX_U on Bottom Layer "NONET_L-01_P-001" (solid, remove dead copper, pour order 20): 1.067,22.809 1.067,7.239 28.092,7.239 28.702,7.849 28.702,22.301 28.194,22.809 27.889,22.809
GND on Bottom Layer "NONET_L-01_P-001" (solid, remove dead copper, pour order 31): 58.268,60.3 58.268,1.118 58.445,0.94 71.069,0.94 71.247,1.118 71.247,60.808 58.776,60.808
GND on Bottom Layer "GND_L04_P066" (solid, remove dead copper, pour order 66): 70.663,47.371 70.663,32.08 73.05,32.08 73.05,47.371
VBAT_D on Bottom Layer "NONET_L-01_P-001" (solid, remove dead copper, pour order 17): 49.657,58.885 49.657,50.8 48.514,49.657 39.218,49.657 38.837,49.276 38.837,43.459 41.097,41.199 47.066,41.199 48.971,39.294 48.971,31.902 47.777,30.709 39.167,30.709 38.633,30.175 38.633,21.285 39.268,20.65 48.616,20.65 49.276,19.99 49.276,12.979 48.539,12.243 31.318,12.243 30.632,11.557 30.632,1.626 31.217,1.041 57.887,1.041 57.988,1.143 57.988,58.869
VBAT_D on Bottom Layer "VBAT_D_L04_P068" (solid, remove dead copper, pour order 68): 55.016,74.803 71.349,74.803 71.425,74.727 71.425,68.224 71.069,67.869 55.016,67.869
GND on Bottom Layer "GND_L04_P069" (solid, remove dead copper, pour order 69): 17.247,72.619 17.247,72.339 30.15,59.436 52.095,59.436 58.42,53.111 66.246,53.111 71.247,58.112 71.247,67.691 71.044,67.894 62.332,67.894 53.95,76.276 19.863,76.276 18.821,75.235
IBS+ on Bottom Layer "IBS+_L04_P015" (solid, remove dead copper, pour order 15): 29.083,57.277 31.039,59.233 49.174,59.233 49.555,58.852 49.555,51.003 48.362,49.809 39.04,49.809 38.405,49.174 38.405,43.434 40.894,40.945 46.584,40.945 48.666,38.862 48.666,32.309 47.346,30.988 39.065,30.988 39.014,31.039 38.405,30.429 38.405,20.955 39.116,20.244 48.542,20.244 49.033,19.752 49.022,19.741 49.022,13.03 48.438,12.446 30.912,12.446 29.083,14.275
GND on L3 "GND_L03_P084" (solid, remove dead copper, pour order 84): 80.733,89.081 80.641,88.989 80.641,84.174 79.241,82.773 72.285,82.773 71.638,82.126 71.638,7.844 72.555,6.927 75.171,6.927 75.964,7.72 79.081,7.72 80.652,6.15 80.652,1.05 81.686,0.016 91.556,0.016 91.585,0.045 125.502,0.045 127.513,2.056 127.513,4.983 129.622,7.091 134.059,7.091 134.975,8.008 134.975,82.376 134.605,82.746 129.962,82.746 127.576,85.133 127.576,89.1 127.575,89.1 126.696,89.98 81.617,89.98 81.617,89.965 80.733,89.081
GND on L3 "GND_L03_P051" (solid, remove dead copper, pour order 51): 57.785,60.3 57.785,1.27 57.988,1.067 71.171,1.067 71.323,1.219 71.298,1.245 71.298,61.036 58.522,61.036
VBAT_D on L3 "VBAT_D_L03_P050" (solid, remove dead copper, pour order 50): 17.297,71.044 16.942,70.688 16.942,7.29 17.043,7.188 28.931,7.188 30.658,5.461 30.658,1.549 31.293,0.914 31.318,0.94 56.464,0.94 57.074,1.549 57.074,60.503 58.064,61.493 70.917,61.493 71.171,61.747 71.171,74.549 51.46,74.549 49.809,72.898 19.152,72.898
VBAT1 on L3 "NONET_L-01_P-001" (solid, remove dead copper, pour order 33): 36.246,88.316 36.246,73.508 50.013,73.508 51.74,75.235 71.145,75.235 71.145,88.316
IBS+ on L3 "NONET_L-01_P-001" (solid, remove dead copper, pour order 24): 37.948,40.462 37.338,40.462 36.881,40.005 36.881,32.029 38.202,30.709 47.93,30.709 49.251,32.029 49.251,39.802 48.618,40.434
IBS+ on L3 "NONET_L-01_P-001" (solid, remove dead copper, pour order 23): 37.135,58.674 36.601,58.141 36.601,50.902 37.44,50.063 48.59,50.063 49.53,51.003 49.53,58.141 48.997,58.674
GND on L3 "NONET_L-01_P-001" (solid, remove dead copper, pour order 34): 0.965,82.708 0.965,71.069 1.092,70.942 18.567,70.942 20.726,73.101 35.408,73.101 35.789,73.482 35.789,87.198 34.372,88.615 28.791,83.16 25.222,83.16 23.368,85.014 23.368,89.306 7.24,89.306 7.24,84.803 5.145,82.708
VPX_U on L3 "VPX_U_L03_P047" (solid, remove dead copper, pour order 47): 23.876,17.755 23.876,13.335 27.838,13.335 27.838,17.755
VPX_V on L3 "VPX_V_L03_P048" (solid, remove dead copper, pour order 48): 23.876,35.623 23.876,31.204 27.838,31.204 27.838,35.623
VPX_W on L3 "VPX_W_L03_P049" (solid, remove dead copper, pour order 49): 23.876,53.492 23.876,49.073 27.838,49.073 27.838,53.492
KL30 on L3 "KL30_L03_P053" (solid, remove dead copper, pour order 53): 1.118,70.637 1.067,70.587 1.067,56.54 16.332,56.54 16.535,56.744 16.535,70.358 16.256,70.637
VPX_W on L3 "VPX_W_L03_P054" (solid, remove dead copper, pour order 54): 1.041,56.032 1.041,38.684 16.612,38.684 16.713,38.786 16.713,55.905 16.586,56.032
VPX_V on L3 "VPX_V_L03_P055" (solid, remove dead copper, pour order 55): 1.067,38.252 1.067,23.317 16.637,23.317 16.739,23.419 16.739,37.973 16.459,38.252
VPX_U on L3 "VPX_U_L03_P056" (solid, remove dead copper, pour order 56): 1.041,22.733 1.041,7.163 16.535,7.163 16.662,7.29 16.662,22.682 16.485,22.86 1.168,22.86
GND on L3 "GND_L03_P060" (solid, remove dead copper, pour order 60): 30.582,89.51 30.582,84.328 32.918,84.328 35.789,87.198 35.789,89.256 35.535,89.51
IBS+ on L3 "IBS+_L03_P046" (solid, remove dead copper, pour order 46): 38.354,19.71 38.354,12.7 38.532,12.522 48.006,12.522 48.59,13.106 48.59,19.837 47.549,20.879 39.548,20.879 38.76,20.091
GND on GND "NONET_L-01_P-001" (solid, remove dead copper, pour order 43): 1.092,82.823 1.092,7.442 1.372,7.163 29.032,7.163 30.937,5.258 30.937,1.397 31.369,0.965 71.069,0.965 71.247,1.143 71.247,89.51 31.115,89.51 30.582,88.976 30.582,84.938 28.804,83.16 25.171,83.16 23.343,84.988 23.343,88.646 22.784,89.205 7.309,89.205 7.309,84.964 5.168,82.823
GND on GND "GND" (solid, remove dead copper, pour order 85): 80.643,88.756 80.643,88.755 80.643,84.177 80.64,84.177 79.236,82.773 72.275,82.773 71.631,82.128 71.631,7.849 72.56,6.92 75.177,6.92 75.964,7.706 79.125,7.706 80.694,6.137 80.694,1.218 81.901,0.011 85.05,0.011 85.055,0.016 85.078,-0.007 125.841,-0.007 127.735,1.887 127.735,5.084 129.824,7.173 133.864,7.173 134.995,8.304 134.995,82.245 134.497,82.743 129.983,82.743 127.579,85.146 127.579,88.887 126.459,90.007 81.432,90.007
VPX_W on GND "NONET_L-01_P-001" (solid, remove dead copper, pour order 35): 23.774,53.518 23.774,49.149 27.737,49.149 27.737,53.518
VPX_V on GND "NONET_L-01_P-001" (solid, remove dead copper, pour order 36): 23.774,35.649 23.774,31.28 27.737,31.28 27.737,35.649
VPX_U on GND "NONET_L-01_P-001" (solid, remove dead copper, pour order 37): 23.774,17.78 23.774,13.411 27.737,13.411 27.737,17.78
VBAT_D on GND "NONET_L-01_P-001" (solid, remove dead copper, pour order 38): 38.151,12.065 37.744,11.659 37.744,7.366 38.43,6.68 46.33,6.68 48.717,9.068 48.717,12.065
VBAT_D on GND "NONET_L-01_P-001" (solid, remove dead copper, pour order 41): 39.116,29.87 39.116,25.73 42.901,25.73 42.901,29.87
VBAT_D on GND "NONET_L-01_P-001" (solid, remove dead copper, pour order 42): 39.116,49.119 39.116,44.979 42.901,44.979 42.901,49.119
IBS+ on GND "IBS+_L02_P016" (solid, remove dead copper, pour order 16): 29.083,57.861 30.455,59.233 49.174,59.233 50.013,58.395 50.013,13.513 48.946,12.446 30.912,12.446 29.083,14.275

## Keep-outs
Keep-Out Layer:
  circle w0.15: c3.5,86.5 r1.75
  circle w0.15: c27,86.5 r1.75
  circle w0.15: c77,86.5 r1.75
  circle w0.15: c77,3.5 r1.75
  circle w0.15: c27,3.5 r1.75
  circle w0.15: c3.5,3.5 r1.75
  lines w0.1: 0,3.448 ccw(c3.5,3.5) 3.5,0 ; 0,86.5 cw(c3.5,86.5) 3.448,90 ; 131.5,90 cw(c131.5,86.5) 135,86.552 ; 131.552,0 ccw(c131.5,3.5) 135,3.5 ; 0,0 135,0 135,90 0,90 0,0

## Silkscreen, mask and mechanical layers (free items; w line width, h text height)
Top Overlay:
  drawing of 1553 lines, arcs and shapes, not listed
  text "VBAT" at 39.99,87.379 h0.6
  text "GND" at 105.301,83.518 h0.6
  text "GND" at 107.865,83.518 h0.6
  text "GND" at 110.393,83.518 h0.6
  text "GND" at 115.54,83.518 h0.6
  text "GND" at 123.236,83.518 h0.6
  text "IO14" at 83.727,83.446 h0.6
  text "IO13" at 86.73,83.44 h0.6
  text "IO12" at 89.175,83.44 h0.6
  text "GND" at 112.977,83.438 h0.6
  text "IO8" at 94.303,83.416 h0.6
  text "IO7" at 96.805,83.419 h0.6
  text "IO9" at 91.789,83.4 h0.6
  text "IO6" at 99.361,83.341 h0.6
  text "EVB_SPD1179DPW56_V1.0" at 50.962,83.113 h0.6
  text "H_A" at 94.346,82.576 h0.6
  text "H_B" at 96.798,82.576 h0.6
  text "H_A" at 99.396,82.576 h0.6
  text "MCUFG" at 83.621,82.476 h0.6
  text "LED1" at 86.789,82.476 h0.6
  text "LED2" at 89.158,82.476 h0.6
  text "LED3" at 91.768,82.476 h0.6
  text "H_A" at 108.203,82.412 h0.6
  text "H_B" at 110.5,82.412 h0.6
  text "H_C" at 112.977,82.412 h0.6
  text "VDD5E" at 104.896,82.312 h0.6
  text "GND" at 115.535,82.312 h0.6
  text "20240712" at 54.411,81.631 h0.6
  text "GND" at 75.401,79.025 h0.6 r90
  text "VDD5" at 122.079,78.934 h0.6
  text "BOOT" at 130.3,78.916 h0.6
  text "TRSTn" at 122.079,76.645 h0.6
  text "MON" at 75.403,76.546 h0.6 r90
  text "GND" at 130.3,76.352 h0.6
  text "VBAT" at 71.725,75.046 h0.6
  text "GND" at 19.264,74.795 h2 r90
  text "VBAT" at 71.732,74.107 h0.6
  text "TDI" at 122.079,73.984 h0.6
  text "GND" at 130.3,73.787 h0.6
  text "VBAT" at 75.344,73.412 h0.6 r90
  text "SWD" at 121.979,71.358 h0.6
  text "RX" at 130.3,71.222 h0.6
  text "SWC" at 121.979,68.838 h0.6
  text "TX" at 130.3,68.657 h0.6
  text "TDO" at 122.079,66.359 h0.6
  text "XRSTn" at 130.3,66.348 h0.6
  text "VDD5" at 122.079,63.879 h0.6
  text "GND" at 130.3,63.683 h0.6
  text "VBAT_IN" at 19.24,60.673 h2 r90
  text "5V_COM" at 124.717,56.936 h0.6 r90
  text "CANH" at 130.529,53.211 h0.6
  text "CANL" at 130.577,50.544 h0.6
  text "VDD5EXT" at 125.338,47.247 h0.6
  text "W" at 19.235,45.149 h2 r90
  text "PWM/LIN" at 125.571,42.079 h0.6
  text "ADC8" at 121.87,34.441 h0.6
  text "GND" at 130.275,34.441 h0.6
  text "ADC7" at 121.87,31.89 h0.6
  text "VDD3" at 130.275,31.89 h0.6
  text "V" at 19.235,30.412 h2 r90
  text "VBAT_DIV" at 130.275,29.538 h0.6
  text "ADC6" at 121.823,29.338 h0.6
  text "ADC5" at 121.67,27.044 h0.6
  text "NTCAD" at 130.275,26.787 h0.6
  text "ADC4" at 121.705,24.389 h0.6
  text "D2SOUT" at 130.275,24.236 h0.6
  text "ADC3" at 121.681,21.899 h0.6
  text "IDC" at 130.275,21.684 h0.6
  text "ADC2" at 121.67,19.35 h0.6
  text "IW" at 130.275,19.133 h0.6
  text "ADC1" at 121.775,16.859 h0.6
  text "IV" at 130.275,16.582 h0.6
  text "U" at 19.236,15.519 h2 r90
  text "ADC0" at 121.658,14.311 h0.6
  text "IU" at 130.275,14.03 h0.6
  text "GND" at 115.848,2.767 h0.6
Bottom Solder:
  rectangle: 55.804,69.266 60.858,74.295
  rectangle: 22.955,48.654 28.01,53.683
  rectangle: 39.211,44.285 44.266,49.314
  rectangle: 22.955,30.785 28.01,35.814
  rectangle: 22.955,12.916 28.01,17.945
  rectangle: 39.211,25.036 44.266,30.066
  rectangle: 39.211,6.788 44.266,11.817
Mechanical 1:
  circle w0.15: c77,86.5 r1.75
  circle w0.15: c77,3.5 r1.75
  circle w0.15: c27,3.5 r1.75
  circle w0.15: c27,86.5 r1.75
  lines w0.1: 0,3.448 ccw(c3.5,3.5) 3.5,0 131.552,0 ccw(c131.5,3.5) 135,3.5 135,86.552 ccw(c131.5,86.5) 131.5,90 3.448,90 ccw(c3.5,86.5) 0,86.5 0,3.448
Mechanical 15:
  lines w0.1: 26.746,3.5 27,3.5 ; 26.8,86.5 27,86.5 ; 27,3.266 27,3.5 ; 27,3.734 27,3.5 ; 27,86.266 27,86.5 ; 27,86.72 27,86.5 ; 27.254,3.5 27,3.5 ; 27.254,86.5 27,86.5 ; 76.766,3.5 77,3.5 ; 76.766,86.5 77,86.5 ; 77,3.246 77,3.5 ; 77,3.734 77,3.5 ; 77,86.246 77,86.5 ; 77,86.8 77,86.5 ; 77.25,86.5 77,86.5 ; 77.272,3.5 77,3.5 ; 19.5,0 19.5,90 84.5,90 84.5,0 19.5,0
  lines w0.254: 120.269,-0.102 120.269,89.713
